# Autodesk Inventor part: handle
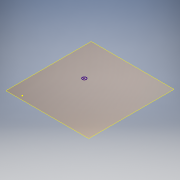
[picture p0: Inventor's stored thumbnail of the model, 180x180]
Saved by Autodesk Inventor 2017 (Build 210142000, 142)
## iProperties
Created: 2017-05
Part Number: handle
Material: Generic
Document SubType Name: Modeling
Designer: 1717440
Density: 1 g/cm^3
Appearance: Default
Author: 1717440
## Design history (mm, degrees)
workplane "Work Plane1"
sketch "Sketch1"
  geometry: C1 r 3.386 at (28.282, 83.089) reference; C2 r 3.486 at (28.282, 83.089); C3 r 5.613 at (28.282, 83.089); 1 further point
  constraints: 3 centre point, 1 coincident, 2 other
  dimensions: "d0" = 0.1 radial gap between concentric circles of C1 C2
workplane "Work Plane2"
extrude "Extrusion1" new body sketch "Sketch1" stored distance "d1" = 10; taper "d2" = 0 deg
sketch "Sketch2"
  geometry: C1 r 5.613 at (0, 0) reference; C2 r 5.613 at (0, 0); 1 further point
  constraints: 1 centre point, 1 coincident, 1 concentric
extrude "Extrusion2" join sketch "Sketch2" distance "d3" = 3; taper "d4" = 0 deg
sketch "Sketch3"
  geometry: L1 (0, 0)-(21, -21); L2 (21.601, -20.399)-(21, -21); L3 (21.601, -20.399)-(2, 2); L4 (20.399, -21.601)-(21, -21); L5 (20.399, -21.601)-(-2, -2); L6 (2, 2)-(-2, -2); C1 r 5.613 at (0, 0) reference; 1 further point
  constraints: 12 end point, 2 symmetric about line
extrude "Extrusion3" join sketch "Sketch3" distance "d5" = 2.5; taper "d6" = 0 deg
sketch "Sketch4"
  geometry: L1 (-1.431, -0.671)-(-2.771, -1.946) reference; L2 (-2.082, -2.67)-(-0.742, -1.396) reference; L3 (-0.742, -1.396)-(-1.431, -0.671) reference; L4 (-0.742, -1.396)-(-2.155, -2.74); L5 (-0.742, -1.396)-(-1.431, -0.671); L6 (-1.431, -0.671)-(-3.206, -2.359); L7 (-0.742, -1.396)-(-2.517, -3.084); L8 (-2.517, -3.084)-(-3.206, -2.359); L9 (-0.884, -1.393)-(-2.234, -2.677); L10 (-2.785, -2.097)-(-1.435, -0.813); L11 (-1.435, -0.813)-(-0.884, -1.393); A1 r 3.386 centre (0, 0) between (-2.082, -2.67) and (-2.771, -1.946) reference; A2 r 3.486 centre (0, 0) between (-2.234, -2.677) and (-2.785, -2.097); 2 further points
  constraints: 16 end point, 3 point on line, 2 point on circle, 1 centre point, 1 collinear, 1 perpendicular, 5 other
  dimensions: "d7" = 0.1 distance between parallel lines of L2 L9
extrude "Extrusion4" join sketch "Sketch4" stored distance "d8" = 2.5; taper "d9" = 0 deg
body "Solid1"
node "Reference1"
